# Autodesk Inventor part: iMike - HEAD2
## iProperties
Shininess: 64.0
Length Units: 11272
Angle Units: 11279
Time Units: 11290
Mass Units: 11286
Length Display Precision: 3
Angle Display Precision: 2
Compacted: True
Part Number: iMike - HEAD2
Document SubType Name: Modeling
Created: 2003-07
Designer: MVF
Manufacturer: Standard
Standards Organization: Custom
Density: 0.0
Volumn: 0.0
Area: 0.0
PropertySet Name: Model Information
Control State: 0
Master: False
Checked Out: False
Author: MVF
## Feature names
1. Revolution1
2. Extrusion1
3. Extrusion2
4. Mirror1
5. Fillet1
6. Revolution2
7. Extrusion3
8. Fillet2
